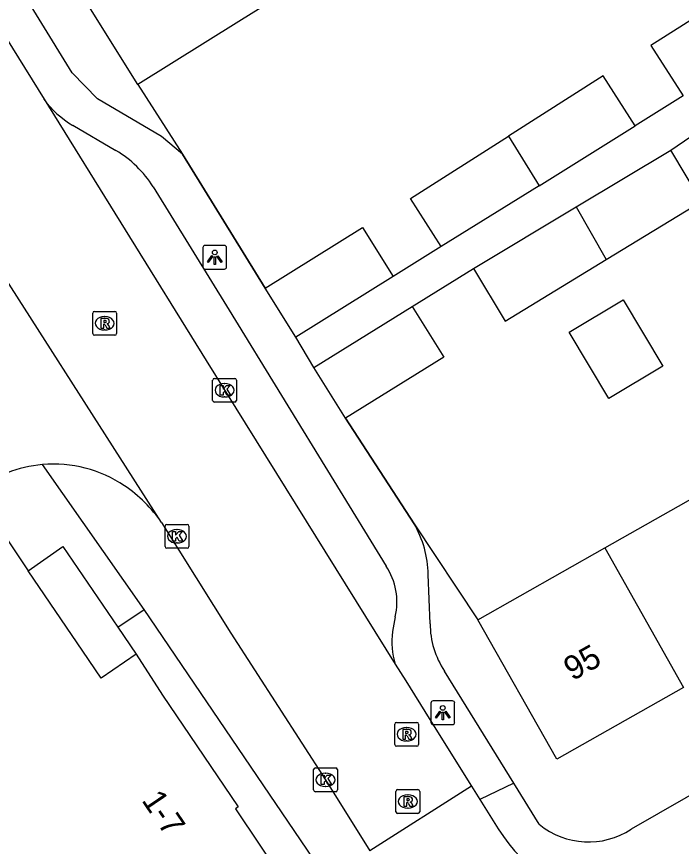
# Model space of a CAD drawing. Extents: x 160037 to 160839, y 385326 to 386441.
# Drawn here: x 160329.8 to 160357.7, y 386041.67 to 386076.5 of the extents above; entities that cross this region are included whole.
import ezdxf

# ---------------------------------------------------------------- set-up
doc = ezdxf.new("R2010")
doc.units = 0
for name, color, linetype in [('IMGEO_Kolk', 7, 'Continuous'), ('IMGEO_Lichtpunt', 7, 'Continuous'), ('IMGEO_Muur', 7, 'Continuous'), ('IMGEO_Pand', 7, 'Continuous'), ('IMGEO_Pand_nummerreeks', 7, 'Continuous'), ('IMGEO_Rijbaan_lokaal_open', 7, 'Continuous'), ('IMGEO_Rioolput', 7, 'Continuous'), ('IMGEO_Voetpad_open', 7, 'Continuous')]:
    doc.layers.add(name, color=color, linetype=linetype)

msp = doc.modelspace()

# ---------------------------------------------------------------- linework, layer by layer
at = {"layer": 'IMGEO_Kolk'}
for p, q in [((160338.031, 386060.389), (160338.031, 386061.241)), ((160338.106, 386061.315), (160338.958, 386061.315)), ((160338.519, 386061.095), (160338.544, 386061.095)), ((160339.032, 386061.241), (160339.032, 386060.389)), ((160338.542, 386060.535), (160338.517, 386060.535)), ((160338.958, 386060.315), (160338.106, 386060.315)), ((160336.031, 386054.258), (160336.031, 386055.11)), ((160336.106, 386055.184), (160336.958, 386055.184)), ((160337.032, 386055.11), (160337.032, 386054.258)), ((160336.519, 386054.964), (160336.544, 386054.964)), ((160336.958, 386054.184), (160336.106, 386054.184)), ((160336.542, 386054.404), (160336.517, 386054.404)), ((160342.267, 386044.036), (160342.267, 386044.888)), ((160342.342, 386044.962), (160343.194, 386044.962)), ((160342.755, 386044.742), (160342.78, 386044.742)), ((160343.268, 386044.888), (160343.268, 386044.036)), ((160342.778, 386044.182), (160342.753, 386044.182)), ((160343.194, 386043.962), (160342.342, 386043.962))]:
    msp.add_line(p, q, dxfattribs=at)
for points in [[(160338.031, 386060.389), (160338.031, 386061.241)], [(160338.106, 386061.315), (160338.958, 386061.315)], [(160339.032, 386061.241), (160339.032, 386060.389)], [(160338.352, 386061.015), (160338.475, 386061.015), (160338.475, 386060.864), (160338.605, 386061.015), (160338.769, 386061.015), (160338.623, 386060.864), (160338.776, 386060.615), (160338.624, 386060.615), (160338.539, 386060.779), (160338.475, 386060.712), (160338.475, 386060.615), (160338.352, 386060.615), (160338.352, 386061.015)], [(160338.958, 386060.315), (160338.106, 386060.315)], [(160336.031, 386054.258), (160336.031, 386055.11)], [(160336.106, 386055.184), (160336.958, 386055.184)], [(160337.032, 386055.11), (160337.032, 386054.258)], [(160336.352, 386054.884), (160336.475, 386054.884), (160336.475, 386054.733), (160336.605, 386054.884), (160336.769, 386054.884), (160336.623, 386054.733), (160336.776, 386054.484), (160336.624, 386054.484), (160336.539, 386054.648), (160336.475, 386054.581), (160336.475, 386054.484), (160336.352, 386054.484), (160336.352, 386054.884)], [(160336.958, 386054.184), (160336.106, 386054.184)], [(160342.267, 386044.036), (160342.267, 386044.888)], [(160342.342, 386044.962), (160343.194, 386044.962)], [(160342.588, 386044.662), (160342.711, 386044.662), (160342.711, 386044.511), (160342.841, 386044.662), (160343.005, 386044.662), (160342.859, 386044.511), (160343.012, 386044.262), (160342.86, 386044.262), (160342.775, 386044.426), (160342.711, 386044.359), (160342.711, 386044.262), (160342.588, 386044.262), (160342.588, 386044.662)], [(160343.268, 386044.888), (160343.268, 386044.036)], [(160343.194, 386043.962), (160342.342, 386043.962)]]:
    msp.add_lwpolyline(points, dxfattribs=at)
for centre, start, end in [((160338.108, 386061.239), 91.552, 178.448), ((160338.108, 386061.239), 91.552, 178.448), ((160338.956, 386061.239), 1.552, 88.448), ((160338.956, 386061.239), 1.552, 88.448), ((160338.108, 386060.391), 181.552, 268.448), ((160338.108, 386060.391), 181.552, 268.448), ((160338.956, 386060.391), 271.552, 358.448), ((160338.956, 386060.391), 271.552, 358.448), ((160336.108, 386055.108), 91.552, 178.448), ((160336.108, 386055.108), 91.552, 178.448), ((160336.956, 386055.108), 1.552, 88.448), ((160336.956, 386055.108), 1.552, 88.448), ((160336.108, 386054.26), 181.552, 268.448), ((160336.108, 386054.26), 181.552, 268.448), ((160336.956, 386054.26), 271.552, 358.448), ((160336.956, 386054.26), 271.552, 358.448), ((160342.344, 386044.886), 91.552, 178.448), ((160342.344, 386044.886), 91.552, 178.448), ((160343.192, 386044.886), 1.552, 88.448), ((160343.192, 386044.886), 1.552, 88.448), ((160342.344, 386044.038), 181.552, 268.448), ((160342.344, 386044.038), 181.552, 268.448), ((160343.192, 386044.038), 271.552, 358.448), ((160343.192, 386044.038), 271.552, 358.448)]:
    msp.add_arc(centre, 0.0765, start, end, dxfattribs=at)
for centre, major_axis, ratio, start_param, end_param in [((160338.518, 386060.815), (-0.387, 0.002), 0.722429, 4.712389, 7.853982), ((160338.543, 386060.815), (-0.39, 0.002), 0.717154, 1.570796, 4.712389), ((160336.518, 386054.684), (-0.387, 0.002), 0.722429, 4.712389, 7.853982), ((160336.543, 386054.684), (-0.39, 0.002), 0.717154, 1.570796, 4.712389), ((160342.754, 386044.462), (-0.387, 0.002), 0.722429, 4.712389, 7.853982), ((160342.779, 386044.462), (-0.39, 0.002), 0.717154, 1.570796, 4.712389)]:
    msp.add_ellipse(centre, major_axis=major_axis, ratio=ratio, start_param=start_param, end_param=end_param, dxfattribs=at)
at = {"layer": 'IMGEO_Lichtpunt'}
for p, q in [((160337.621, 386066.802), (160337.621, 386065.995)), ((160337.621, 386066.802), (160337.621, 386065.995)), ((160338.523, 386066.897), (160337.715, 386066.897)), ((160338.523, 386066.897), (160337.715, 386066.897)), ((160338.617, 386065.995), (160338.617, 386066.802)), ((160338.617, 386065.995), (160338.617, 386066.802)), ((160337.715, 386065.901), (160338.523, 386065.901)), ((160337.715, 386065.901), (160338.523, 386065.901)), ((160347.19, 386047.681), (160347.19, 386046.874)), ((160347.19, 386047.681), (160347.19, 386046.874)), ((160348.092, 386047.776), (160347.284, 386047.776)), ((160348.092, 386047.776), (160347.284, 386047.776)), ((160348.186, 386046.874), (160348.186, 386047.681)), ((160348.186, 386046.874), (160348.186, 386047.681)), ((160347.284, 386046.78), (160348.092, 386046.78)), ((160347.284, 386046.78), (160348.092, 386046.78))]:
    msp.add_line(p, q, dxfattribs=at)
for points in [[(160337.995, 386066.466), (160338.034, 386066.438), (160337.846, 386066.176), (160337.808, 386066.203), (160337.995, 386066.466)], [(160338.097, 386066.418), (160338.144, 386066.418), (160338.144, 386066.096), (160338.097, 386066.096), (160338.097, 386066.418)], [(160338.207, 386066.438), (160338.245, 386066.465), (160338.432, 386066.203), (160338.393, 386066.175), (160338.207, 386066.438)], [(160347.564, 386047.345), (160347.603, 386047.317), (160347.415, 386047.055), (160347.377, 386047.082), (160347.564, 386047.345)], [(160347.666, 386047.297), (160347.713, 386047.297), (160347.713, 386046.975), (160347.666, 386046.975), (160347.666, 386047.297)], [(160347.776, 386047.317), (160347.814, 386047.344), (160348.001, 386047.082), (160347.962, 386047.054), (160347.776, 386047.317)]]:
    msp.add_lwpolyline(points, dxfattribs=at)
for centre in [(160338.12, 386066.6), (160347.689, 386047.479)]:
    msp.add_circle(centre, 0.0994, dxfattribs=at)
for centre, start, end in [((160337.715, 386066.802), 90, 180), ((160337.715, 386066.802), 90, 180), ((160338.523, 386066.802), 0, 90), ((160338.523, 386066.802), 0, 90), ((160337.715, 386065.995), 180, 270), ((160337.715, 386065.995), 180, 270), ((160338.523, 386065.995), 270, 0), ((160338.523, 386065.995), 270, 360), ((160347.284, 386047.681), 90, 180), ((160347.284, 386047.681), 90, 180), ((160348.092, 386047.681), 0, 90), ((160348.092, 386047.681), 0, 90), ((160347.284, 386046.874), 180, 270), ((160347.284, 386046.874), 180, 270), ((160348.092, 386046.874), 270, 0), ((160348.092, 386046.874), 270, 360)]:
    msp.add_arc(centre, 0.0946, start, end, dxfattribs=at)
at = {"layer": 'IMGEO_Muur'}
for points in [[(160334.888, 386073.656), (160336.764, 386070.723)], [(160336.764, 386070.723), (160340.233, 386065.107)], [(160343.602, 386059.637), (160346.483, 386055.214)], [(160346.483, 386055.214), (160349.158, 386051.183)]]:
    msp.add_lwpolyline(points, dxfattribs=at)
at = {"layer": 'IMGEO_Pand'}
for points in [[(160340.046, 386076.87), (160339.132, 386076.301), (160334.888, 386073.656), (160330.88, 386080.092), (160336.058, 386083.302)], [(160360.53, 386077.911), (160356.424, 386075.292), (160357.776, 386073.171)], [(160355.758, 386071.914), (160354.419, 386074.013), (160350.444, 386071.478)], [(160351.729, 386069.404), (160355.758, 386071.914)], [(160347.624, 386066.847), (160346.34, 386068.859), (160350.444, 386071.478)], [(160350.444, 386071.478), (160351.729, 386069.404)], [(160353.292, 386068.509), (160357.26, 386070.889)], [(160354.54, 386066.3), (160358.55, 386068.739), (160357.26, 386070.889)], [(160351.729, 386069.404), (160347.624, 386066.847)], [(160348.979, 386065.922), (160353.292, 386068.509)], [(160353.292, 386068.509), (160354.54, 386066.3)], [(160340.233, 386065.107), (160344.314, 386067.649), (160345.599, 386065.586)], [(160348.979, 386065.922), (160350.301, 386063.721), (160354.54, 386066.3)], [(160345.599, 386065.586), (160341.518, 386063.044)], [(160341.518, 386063.044), (160340.233, 386065.107)], [(160356.92, 386061.832), (160354.656, 386060.473), (160352.988, 386063.249), (160355.253, 386064.609), (160356.92, 386061.832)], [(160342.276, 386061.767), (160346.4, 386064.336)], [(160346.4, 386064.336), (160347.726, 386062.206), (160343.602, 386059.637)], [(160343.602, 386059.637), (160342.276, 386061.767)], [(160354.485, 386054.195), (160359.708, 386057.149)], [(160265.499, 386011.79), (160329.094, 386054.994), (160330.293, 386053.228)], [(160357.796, 386048.34), (160352.469, 386045.329), (160349.158, 386051.183), (160354.485, 386054.195)], [(160354.485, 386054.195), (160357.796, 386048.34)], [(160334.826, 386049.73), (160333.35, 386048.728), (160332.578, 386049.864), (160330.293, 386053.228)], [(160334.826, 386049.73), (160335.927, 386048.015), (160339.1, 386043.322), (160338.986, 386043.242), (160342.054, 386038.664)]]:
    msp.add_lwpolyline(points, dxfattribs=at)
at = {"layer": 'IMGEO_Rijbaan_lokaal_open'}
for points in [[(160326.703, 386079.873), (160330.953, 386073.039)], [(160330.953, 386073.039), (160337.757, 386062.058), (160345.695, 386049.312)], [(160335.889, 386055.264), (160327.523, 386068.337)], [(160335.889, 386055.264), (160338.797, 386050.618), (160342.768, 386044.462), (160344.631, 386041.482)], [(160345.695, 386049.312), (160346.132, 386048.61), (160347.11, 386047.04), (160348.891, 386044.19)], [(160348.891, 386044.19), (160344.631, 386041.482)], [(160348.891, 386044.19), (160349.237, 386043.638)], [(160349.237, 386043.638), (160350.013, 386042.398)]]:
    msp.add_lwpolyline(points, dxfattribs=at)
for centre, radius, start, end in [((160331.357, 386052.378), 5.338, 95.0555, 127.5647), ((160331.356, 386052.375), 5.34, 56.1425, 95.0347), ((160330.873, 386051.767), 6.114, 34.8813, 55.5617), ((160356.41, 386046.506), 7.602, 212.706, 301.346)]:
    msp.add_arc(centre, radius, start, end, dxfattribs=at)
at = {"layer": 'IMGEO_Rioolput'}
for p, q in [((160332.998, 386063.2), (160332.998, 386064.052)), ((160333.073, 386064.126), (160333.925, 386064.126)), ((160333.486, 386063.906), (160333.511, 386063.906)), ((160333.999, 386064.052), (160333.999, 386063.2)), ((160333.925, 386063.126), (160333.073, 386063.126)), ((160333.509, 386063.346), (160333.484, 386063.346)), ((160345.669, 386045.947), (160345.669, 386046.799)), ((160345.744, 386046.873), (160346.596, 386046.873)), ((160346.67, 386046.799), (160346.67, 386045.947)), ((160346.157, 386046.653), (160346.182, 386046.653)), ((160346.18, 386046.093), (160346.155, 386046.093)), ((160346.596, 386045.873), (160345.744, 386045.873)), ((160345.718, 386043.124), (160345.718, 386043.976)), ((160345.793, 386044.05), (160346.645, 386044.05)), ((160346.719, 386043.976), (160346.719, 386043.124)), ((160346.206, 386043.83), (160346.231, 386043.83)), ((160346.229, 386043.27), (160346.204, 386043.27)), ((160346.645, 386043.05), (160345.793, 386043.05))]:
    msp.add_line(p, q, dxfattribs=at)
for points in [[(160332.998, 386063.2), (160332.998, 386064.052)], [(160333.073, 386064.126), (160333.925, 386064.126)], [(160333.587, 386063.824), (160333.335, 386063.826), (160333.335, 386063.426)], [(160333.999, 386064.052), (160333.999, 386063.2)], [(160333.335, 386063.426), (160333.459, 386063.426), (160333.459, 386063.588), (160333.47, 386063.588)], [(160333.513, 386063.745), (160333.459, 386063.745), (160333.459, 386063.664)], [(160333.459, 386063.664), (160333.511, 386063.664)], [(160333.517, 386063.559), (160333.588, 386063.426), (160333.728, 386063.426), (160333.663, 386063.552)], [(160333.925, 386063.126), (160333.073, 386063.126)], [(160345.669, 386045.947), (160345.669, 386046.799)], [(160345.744, 386046.873), (160346.596, 386046.873)], [(160346.67, 386046.799), (160346.67, 386045.947)], [(160346.258, 386046.571), (160346.006, 386046.573), (160346.006, 386046.173)], [(160346.184, 386046.492), (160346.13, 386046.492), (160346.13, 386046.411)], [(160346.13, 386046.411), (160346.182, 386046.411)], [(160346.006, 386046.173), (160346.13, 386046.173), (160346.13, 386046.335), (160346.141, 386046.335)], [(160346.188, 386046.306), (160346.259, 386046.173), (160346.399, 386046.173), (160346.334, 386046.299)], [(160346.596, 386045.873), (160345.744, 386045.873)], [(160345.718, 386043.124), (160345.718, 386043.976)], [(160345.793, 386044.05), (160346.645, 386044.05)], [(160346.719, 386043.976), (160346.719, 386043.124)], [(160346.307, 386043.748), (160346.055, 386043.75), (160346.055, 386043.35)], [(160346.233, 386043.669), (160346.179, 386043.669), (160346.179, 386043.588)], [(160346.055, 386043.35), (160346.179, 386043.35), (160346.179, 386043.512), (160346.19, 386043.512)], [(160346.179, 386043.588), (160346.231, 386043.588)], [(160346.237, 386043.483), (160346.308, 386043.35), (160346.448, 386043.35), (160346.383, 386043.476)], [(160346.645, 386043.05), (160345.793, 386043.05)]]:
    msp.add_lwpolyline(points, dxfattribs=at)
for centre, radius, start, end in [((160333.075, 386064.05), 0.0765, 91.552, 178.448), ((160333.075, 386064.05), 0.0765, 91.552, 178.448), ((160333.586, 386063.714), 0.109, 350.3612, 89.416), ((160333.923, 386064.05), 0.0765, 1.552, 88.448), ((160333.923, 386064.05), 0.0765, 1.552, 88.448), ((160333.469, 386063.535), 0.0533, 26.0293, 88.6989), ((160333.495, 386063.853), 0.19, 274.7715, 282.9687), ((160333.519, 386063.649), 0.0964, 77.0061, 93.1865), ((160333.533, 386063.706), 0.0378, 276.6634, 79.6772), ((160333.584, 386063.714), 0.112, 277.5842, 350.9817), ((160333.568, 386063.499), 0.108, 29.5134, 73.7905), ((160333.075, 386063.202), 0.0765, 181.552, 268.448), ((160333.075, 386063.202), 0.0765, 181.552, 268.448), ((160333.923, 386063.202), 0.0765, 271.552, 358.448), ((160333.923, 386063.202), 0.0765, 271.552, 358.448), ((160345.746, 386046.797), 0.0765, 91.552, 178.448), ((160345.746, 386046.797), 0.0765, 91.552, 178.448), ((160346.594, 386046.797), 0.0765, 1.552, 88.448), ((160346.594, 386046.797), 0.0765, 1.552, 88.448), ((160346.166, 386046.6), 0.19, 274.7715, 282.9687), ((160346.19, 386046.396), 0.0964, 77.0061, 93.1865), ((160346.204, 386046.453), 0.0378, 276.6634, 79.6772), ((160346.257, 386046.461), 0.109, 350.3612, 89.416), ((160346.255, 386046.461), 0.112, 277.5842, 350.9817), ((160346.14, 386046.282), 0.0533, 26.0293, 88.6989), ((160346.239, 386046.246), 0.108, 29.5134, 73.7905), ((160345.746, 386045.949), 0.0765, 181.552, 268.448), ((160345.746, 386045.949), 0.0765, 181.552, 268.448), ((160346.594, 386045.949), 0.0765, 271.552, 358.448), ((160346.594, 386045.949), 0.0765, 271.552, 358.448), ((160345.795, 386043.974), 0.0765, 91.552, 178.448), ((160345.795, 386043.974), 0.0765, 91.552, 178.448), ((160346.643, 386043.974), 0.0765, 1.552, 88.448), ((160346.643, 386043.974), 0.0765, 1.552, 88.448), ((160346.239, 386043.573), 0.0964, 77.0061, 93.1865), ((160346.253, 386043.63), 0.0378, 276.6634, 79.6772), ((160346.306, 386043.638), 0.109, 350.3612, 89.416), ((160346.304, 386043.638), 0.112, 277.5842, 350.9817), ((160346.189, 386043.459), 0.0533, 26.0293, 88.6989), ((160346.215, 386043.777), 0.19, 274.7715, 282.9687), ((160346.288, 386043.423), 0.108, 29.5134, 73.7905), ((160345.795, 386043.126), 0.0765, 181.552, 268.448), ((160345.795, 386043.126), 0.0765, 181.552, 268.448), ((160346.643, 386043.126), 0.0765, 271.552, 358.448), ((160346.643, 386043.126), 0.0765, 271.552, 358.448)]:
    msp.add_arc(centre, radius, start, end, dxfattribs=at)
for centre, major_axis, ratio, start_param, end_param in [((160333.485, 386063.626), (-0.387, 0.002), 0.722429, 4.712389, 7.853982), ((160333.51, 386063.626), (-0.39, 0.002), 0.717154, 1.570796, 4.712389), ((160346.156, 386046.373), (-0.387, 0.002), 0.722429, 4.712389, 7.853982), ((160346.181, 386046.373), (-0.39, 0.002), 0.717154, 1.570796, 4.712389), ((160346.205, 386043.55), (-0.387, 0.002), 0.722429, 4.712389, 7.853982), ((160346.23, 386043.55), (-0.39, 0.002), 0.717154, 1.570796, 4.712389)]:
    msp.add_ellipse(centre, major_axis=major_axis, ratio=ratio, start_param=start_param, end_param=end_param, dxfattribs=at)
at = {"layer": 'IMGEO_Voetpad_open'}
for points in [[(160340.233, 386065.107), (160336.764, 386070.723), (160335.878, 386071.475), (160333.192, 386073.046), (160332.134, 386074.146), (160327.964, 386080.916)], [(160413.098, 386074.945), (160376.029, 386054.076), (160361.429, 386045.73), (160355.592, 386042.393)], [(160357.776, 386073.171), (160355.758, 386071.914)], [(160357.26, 386070.889), (160359.198, 386072.224)], [(160332.159, 386071.937), (160333.971, 386070.877)], [(160335.528, 386069.358), (160338.728, 386064.177), (160345.306, 386053.436)], [(160347.624, 386066.847), (160345.599, 386065.586)], [(160346.4, 386064.336), (160348.979, 386065.922)], [(160342.276, 386061.767), (160341.518, 386063.044)], [(160346.483, 386055.214), (160343.602, 386059.637)], [(160335.152, 386051.612), (160330.887, 386057.695)], [(160330.293, 386053.228), (160331.749, 386054.258), (160334.054, 386050.866)], [(160347.158, 386051.016), (160347.08, 386053.085)], [(160334.054, 386050.866), (160335.152, 386051.612)], [(160343.316, 386039.594), (160335.152, 386051.612)], [(160345.689, 386051.307), (160345.577, 386050.681)], [(160334.054, 386050.866), (160334.826, 386049.73)], [(160350.671, 386044.32), (160347.765, 386049.027)], [(160350.671, 386044.32), (160349.237, 386043.638)], [(160351.736, 386042.596), (160350.671, 386044.32)]]:
    msp.add_lwpolyline(points, dxfattribs=at)
for centre, radius, start, end in [((160334.132, 386075.307), 3.906, 215.5081, 239.652), ((160331.706, 386066.998), 4.492, 31.6965, 59.719), ((160342.575, 386052.97), 4.507, 1.4643, 29.8641), ((160343.035, 386051.929), 2.726, 346.8193, 33.5771), ((160350.628, 386050.988), 3.47, 179.5363, 214.4059), ((160348.681, 386050.259), 3.132, 172.2566, 197.5962), ((160353.801, 386045.091), 3.239, 230.3919, 303.581)]:
    msp.add_arc(centre, radius, start, end, dxfattribs=at)

# ---------------------------------------------------------------- texts
at = {"layer": 'IMGEO_Pand_nummerreeks'}
for s, rotation, p in [('95', 29.4444, (160353.129, 386048.595)), ('1-7', 304.1882, (160335.025, 386043.6))]:
    msp.add_text(s, height=1, rotation=rotation, dxfattribs=at).set_placement(p)

doc.saveas('drawing.dxf')
